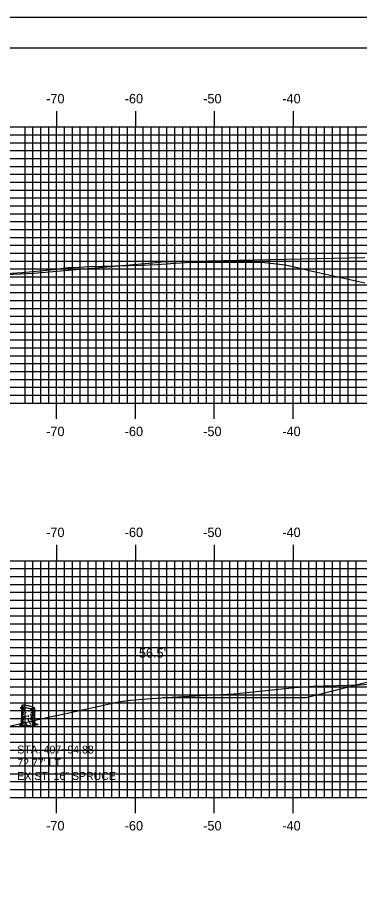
# Model space of a CAD drawing. Extents: x 852529 to 852872, y 364785 to 365005.
# Drawn here: x 852619.8 to 852663.2, y 364894.2 to 365005.1 of the extents above; entities that cross this region are included whole.
import ezdxf

# ---------------------------------------------------------------- set-up
doc = ezdxf.new("R2010")
doc.units = 0
for name, color, linetype in [('ANNOTATION', 7, 'Continuous'), ('BORDER', 7, 'Continuous'), ('D_Text_Monospaced', 7, 'Continuous'), ('D_Text_Standard', 7, 'Continuous'), ('H_V ANNOTATION', 7, 'Continuous'), ('MAJOR', 7, 'Continuous'), ('MINOR', 7, 'Continuous'), ('PLOT BOUNDARY', 7, 'Continuous'), ('S_Roadway_Centerline', 7, 'Continuous'), ('S_Trees_Conifer_Pay', 7, 'Continuous')]:
    doc.layers.add(name, color=color, linetype=linetype)

msp = doc.modelspace()

# ---------------------------------------------------------------- linework, layer by layer
at = {"layer": 'ANNOTATION'}
for p, q in [((852663.86, 364974.63), (852637.93, 364974.11)), ((852656.38, 364918.85), (852638.2, 364918.84))]:
    msp.add_line(p, q, dxfattribs=at)
for points in [[(852610.41, 364972.14), (852621.84, 364972.69), (852637.93, 364974.11)], [(852673.13, 364923.04), (852669.13, 364922.04), (852656.38, 364918.85)]]:
    msp.add_lwpolyline(points, dxfattribs=at)
at = {"layer": 'BORDER'}
msp.add_lwpolyline([(852545.13, 364791.23), (852865.13, 364791.23), (852865.13, 365001.23), (852545.13, 365001.23)], close=True, dxfattribs=at)
at = {"layer": 'MAJOR'}
for p, q in [((852624.73, 364993.24), (852624.73, 364991.23)), ((852634.73, 364993.24), (852634.73, 364991.23)), ((852644.73, 364993.24), (852644.73, 364991.23)), ((852654.73, 364993.24), (852654.73, 364991.23)), ((852554.73, 364991.23), (852834.73, 364991.23)), ((852554.73, 364991.23), (852834.73, 364991.23)), ((852624.73, 364956.23), (852624.73, 364991.23)), ((852634.73, 364956.23), (852634.73, 364991.23)), ((852644.73, 364956.23), (852644.73, 364991.23)), ((852654.73, 364956.23), (852654.73, 364991.23)), ((852554.73, 364986.23), (852834.73, 364986.23)), ((852554.73, 364981.23), (852834.73, 364981.23)), ((852554.73, 364976.23), (852834.73, 364976.23)), ((852554.73, 364971.23), (852834.73, 364971.23)), ((852554.73, 364966.23), (852834.73, 364966.23)), ((852554.73, 364961.23), (852834.73, 364961.23)), ((852554.73, 364956.23), (852834.73, 364956.23)), ((852554.73, 364956.23), (852834.73, 364956.23)), ((852624.73, 364954.23), (852624.73, 364956.23)), ((852634.73, 364954.23), (852634.73, 364956.23)), ((852644.73, 364954.23), (852644.73, 364956.23)), ((852654.73, 364954.23), (852654.73, 364956.23)), ((852624.73, 364938.24), (852624.73, 364936.23)), ((852634.73, 364938.24), (852634.73, 364936.23)), ((852644.73, 364938.24), (852644.73, 364936.23)), ((852654.73, 364938.24), (852654.73, 364936.23)), ((852554.73, 364936.23), (852834.73, 364936.23)), ((852554.73, 364936.23), (852834.73, 364936.23)), ((852624.73, 364906.23), (852624.73, 364936.23)), ((852634.73, 364906.23), (852634.73, 364936.23)), ((852644.73, 364906.23), (852644.73, 364936.23)), ((852654.73, 364906.23), (852654.73, 364936.23)), ((852554.73, 364931.23), (852834.73, 364931.23)), ((852554.73, 364926.23), (852834.73, 364926.23)), ((852554.73, 364921.23), (852834.73, 364921.23)), ((852554.73, 364916.23), (852834.73, 364916.23)), ((852554.73, 364911.23), (852834.73, 364911.23)), ((852554.73, 364906.23), (852834.73, 364906.23)), ((852554.73, 364906.23), (852834.73, 364906.23)), ((852624.73, 364904.23), (852624.73, 364906.23)), ((852634.73, 364904.23), (852634.73, 364906.23)), ((852644.73, 364904.23), (852644.73, 364906.23)), ((852654.73, 364904.23), (852654.73, 364906.23))]:
    msp.add_line(p, q, dxfattribs=at)
at = {"layer": 'MINOR'}
for p, q in [((852620.73, 364956.23), (852620.73, 364991.23)), ((852621.73, 364956.23), (852621.73, 364991.23)), ((852622.73, 364956.23), (852622.73, 364991.23)), ((852623.73, 364956.23), (852623.73, 364991.23)), ((852625.73, 364956.23), (852625.73, 364991.23)), ((852626.73, 364956.23), (852626.73, 364991.23)), ((852627.73, 364956.23), (852627.73, 364991.23)), ((852628.73, 364956.23), (852628.73, 364991.23)), ((852629.73, 364956.23), (852629.73, 364991.23)), ((852630.73, 364956.23), (852630.73, 364991.23)), ((852631.73, 364956.23), (852631.73, 364991.23)), ((852632.73, 364956.23), (852632.73, 364991.23)), ((852633.73, 364956.23), (852633.73, 364991.23)), ((852635.73, 364956.23), (852635.73, 364991.23)), ((852636.73, 364956.23), (852636.73, 364991.23)), ((852637.73, 364956.23), (852637.73, 364991.23)), ((852638.73, 364956.23), (852638.73, 364991.23)), ((852639.73, 364956.23), (852639.73, 364991.23)), ((852640.73, 364956.23), (852640.73, 364991.23)), ((852641.73, 364956.23), (852641.73, 364991.23)), ((852642.73, 364956.23), (852642.73, 364991.23)), ((852643.73, 364956.23), (852643.73, 364991.23)), ((852645.73, 364956.23), (852645.73, 364991.23)), ((852646.73, 364956.23), (852646.73, 364991.23)), ((852647.73, 364956.23), (852647.73, 364991.23)), ((852648.73, 364956.23), (852648.73, 364991.23)), ((852649.73, 364956.23), (852649.73, 364991.23)), ((852650.73, 364956.23), (852650.73, 364991.23)), ((852651.73, 364956.23), (852651.73, 364991.23)), ((852652.73, 364956.23), (852652.73, 364991.23)), ((852653.73, 364956.23), (852653.73, 364991.23)), ((852655.73, 364956.23), (852655.73, 364991.23)), ((852656.73, 364956.23), (852656.73, 364991.23)), ((852657.73, 364956.23), (852657.73, 364991.23)), ((852658.73, 364956.23), (852658.73, 364991.23)), ((852659.73, 364956.23), (852659.73, 364991.23)), ((852660.73, 364956.23), (852660.73, 364991.23)), ((852661.73, 364956.23), (852661.73, 364991.23)), ((852662.73, 364956.23), (852662.73, 364991.23)), ((852554.73, 364990.23), (852834.73, 364990.23)), ((852554.73, 364989.23), (852834.73, 364989.23)), ((852554.73, 364988.23), (852834.73, 364988.23)), ((852554.73, 364987.23), (852834.73, 364987.23)), ((852554.73, 364985.23), (852834.73, 364985.23)), ((852554.73, 364984.23), (852834.73, 364984.23)), ((852554.73, 364983.23), (852834.73, 364983.23)), ((852554.73, 364982.23), (852834.73, 364982.23)), ((852554.73, 364980.23), (852834.73, 364980.23)), ((852554.73, 364979.23), (852834.73, 364979.23)), ((852554.73, 364978.23), (852834.73, 364978.23)), ((852554.73, 364977.23), (852834.73, 364977.23)), ((852554.73, 364975.23), (852834.73, 364975.23)), ((852554.73, 364974.23), (852834.73, 364974.23)), ((852554.73, 364973.23), (852834.73, 364973.23)), ((852554.73, 364972.23), (852834.73, 364972.23)), ((852554.73, 364970.23), (852834.73, 364970.23)), ((852554.73, 364969.23), (852834.73, 364969.23)), ((852554.73, 364968.23), (852834.73, 364968.23)), ((852554.73, 364967.23), (852834.73, 364967.23)), ((852554.73, 364965.23), (852834.73, 364965.23)), ((852554.73, 364964.23), (852834.73, 364964.23)), ((852554.73, 364963.23), (852834.73, 364963.23)), ((852554.73, 364962.23), (852834.73, 364962.23)), ((852554.73, 364960.23), (852834.73, 364960.23)), ((852554.73, 364959.23), (852834.73, 364959.23)), ((852554.73, 364958.23), (852834.73, 364958.23)), ((852554.73, 364957.23), (852834.73, 364957.23)), ((852620.73, 364906.23), (852620.73, 364936.23)), ((852621.73, 364906.23), (852621.73, 364936.23)), ((852622.73, 364906.23), (852622.73, 364936.23)), ((852623.73, 364906.23), (852623.73, 364936.23)), ((852625.73, 364906.23), (852625.73, 364936.23)), ((852626.73, 364906.23), (852626.73, 364936.23)), ((852627.73, 364906.23), (852627.73, 364936.23)), ((852628.73, 364906.23), (852628.73, 364936.23)), ((852629.73, 364906.23), (852629.73, 364936.23)), ((852630.73, 364906.23), (852630.73, 364936.23)), ((852631.73, 364906.23), (852631.73, 364936.23)), ((852632.73, 364906.23), (852632.73, 364936.23)), ((852633.73, 364906.23), (852633.73, 364936.23)), ((852635.73, 364906.23), (852635.73, 364936.23)), ((852636.73, 364906.23), (852636.73, 364936.23)), ((852637.73, 364906.23), (852637.73, 364936.23)), ((852638.73, 364906.23), (852638.73, 364936.23)), ((852639.73, 364906.23), (852639.73, 364936.23)), ((852640.73, 364906.23), (852640.73, 364936.23)), ((852641.73, 364906.23), (852641.73, 364936.23)), ((852642.73, 364906.23), (852642.73, 364936.23)), ((852643.73, 364906.23), (852643.73, 364936.23)), ((852645.73, 364906.23), (852645.73, 364936.23)), ((852646.73, 364906.23), (852646.73, 364936.23)), ((852647.73, 364906.23), (852647.73, 364936.23)), ((852648.73, 364906.23), (852648.73, 364936.23)), ((852649.73, 364906.23), (852649.73, 364936.23)), ((852650.73, 364906.23), (852650.73, 364936.23)), ((852651.73, 364906.23), (852651.73, 364936.23)), ((852652.73, 364906.23), (852652.73, 364936.23)), ((852653.73, 364906.23), (852653.73, 364936.23)), ((852655.73, 364906.23), (852655.73, 364936.23)), ((852656.73, 364906.23), (852656.73, 364936.23)), ((852657.73, 364906.23), (852657.73, 364936.23)), ((852658.73, 364906.23), (852658.73, 364936.23)), ((852659.73, 364906.23), (852659.73, 364936.23)), ((852660.73, 364906.23), (852660.73, 364936.23)), ((852661.73, 364906.23), (852661.73, 364936.23)), ((852662.73, 364906.23), (852662.73, 364936.23)), ((852554.73, 364935.23), (852834.73, 364935.23)), ((852554.73, 364934.23), (852834.73, 364934.23)), ((852554.73, 364933.23), (852834.73, 364933.23)), ((852554.73, 364932.23), (852834.73, 364932.23)), ((852554.73, 364930.23), (852834.73, 364930.23)), ((852554.73, 364929.23), (852834.73, 364929.23)), ((852554.73, 364928.23), (852834.73, 364928.23)), ((852554.73, 364927.23), (852834.73, 364927.23)), ((852554.73, 364925.23), (852834.73, 364925.23)), ((852554.73, 364924.23), (852834.73, 364924.23)), ((852554.73, 364923.23), (852834.73, 364923.23)), ((852554.73, 364922.23), (852834.73, 364922.23)), ((852554.73, 364920.23), (852834.73, 364920.23)), ((852554.73, 364919.23), (852834.73, 364919.23)), ((852554.73, 364918.23), (852834.73, 364918.23)), ((852554.73, 364917.23), (852834.73, 364917.23)), ((852554.73, 364915.23), (852834.73, 364915.23)), ((852554.73, 364914.23), (852834.73, 364914.23)), ((852554.73, 364913.23), (852834.73, 364913.23)), ((852554.73, 364912.23), (852834.73, 364912.23)), ((852554.73, 364910.23), (852834.73, 364910.23)), ((852554.73, 364909.23), (852834.73, 364909.23)), ((852554.73, 364908.23), (852834.73, 364908.23)), ((852554.73, 364907.23), (852834.73, 364907.23))]:
    msp.add_line(p, q, dxfattribs=at)
at = {"layer": 'PLOT BOUNDARY'}
msp.add_lwpolyline([(852528.94, 364785.11), (852868.94, 364785.11), (852868.94, 365005.11), (852528.94, 365005.11)], close=True, dxfattribs=at)
at = {"layer": 'S_Roadway_Centerline'}
for points in [[(852610.84, 364972.19), (852620.36, 364972.79), (852624.32, 364973.16), (852626.18, 364973.4), (852626.86, 364973.43), (852628.9, 364973.52), (852635.5, 364973.73), (852637.51, 364973.8), (852637.99, 364973.83), (852641.71, 364974.09), (852649.77, 364974.09), (852650.73, 364974.09), (852653.38, 364973.78), (852653.64, 364973.75), (852653.75, 364973.77), (852654.14, 364973.68), (852656.37, 364973.17), (852656.63, 364973.07), (852663.86, 364971.49)], [(852610.61, 364913.39), (852623.86, 364916.43), (852624.73, 364916.6), (852625.73, 364916.82), (852632.57, 364918.34), (852634.09, 364918.54), (852636.22, 364918.74), (852638.65, 364918.87), (852643.03, 364919.13), (852647.2, 364919.36), (852654.94, 364920.14), (852657.27, 364920.33), (852663.16, 364920.51), (852665.08, 364920.61)]]:
    msp.add_lwpolyline(points, dxfattribs=at)
at = {"layer": 'S_Trees_Conifer_Pay'}
for p, q in [((852620.3, 364916.21), (852620.3, 364917.85)), ((852620.37, 364917.78), (852620.37, 364917.62)), ((852620.37, 364917.55), (852620.37, 364917.42)), ((852620.49, 364917.72), (852620.49, 364917.5)), ((852620.49, 364917.41), (852620.49, 364917.36)), ((852620.71, 364917.52), (852620.71, 364917.32)), ((852621.51, 364917.48), (852621.51, 364917.31)), ((852621.73, 364917.46), (852621.73, 364917.23)), ((852621.86, 364917.47), (852621.86, 364917.37)), ((852621.91, 364917.48), (852621.91, 364917.01)), ((852621.96, 364915.8), (852621.96, 364917.52)), ((852620.37, 364917.24), (852620.37, 364916.9)), ((852620.37, 364916.86), (852620.37, 364916.7)), ((852620.37, 364916.65), (852620.37, 364916.44)), ((852620.37, 364916.41), (852620.37, 364916.33)), ((852620.37, 364916.29), (852620.37, 364916.12)), ((852620.43, 364917.23), (852620.48, 364917.17)), ((852620.49, 364917.03), (852620.49, 364916.89)), ((852620.49, 364916.78), (852620.49, 364916.67)), ((852620.49, 364916.54), (852620.49, 364916.4)), ((852620.71, 364917.27), (852620.71, 364917.18)), ((852620.71, 364916.83), (852620.71, 364916.73)), ((852620.71, 364916.36), (852620.71, 364916.21)), ((852621.11, 364917.25), (852621.11, 364917.16)), ((852621.11, 364916.64), (852621.11, 364916.56)), ((852621.11, 364916.54), (852621.11, 364916.39)), ((852621.51, 364917.08), (852621.51, 364916.84)), ((852621.51, 364916.6), (852621.51, 364916.44)), ((852621.51, 364916.4), (852621.51, 364916.23)), ((852621.73, 364917.19), (852621.73, 364917.11)), ((852621.73, 364916.71), (852621.73, 364916.57)), ((852621.73, 364916.3), (852621.73, 364916.16)), ((852621.86, 364917.3), (852621.86, 364917.09)), ((852621.86, 364917.04), (852621.86, 364916.84)), ((852621.86, 364916.79), (852621.86, 364916.45)), ((852621.86, 364916.4), (852621.86, 364916.26)), ((852621.91, 364916.95), (852621.91, 364916.64)), ((852621.91, 364916.59), (852621.91, 364916.1)), ((852620.49, 364916.17), (852620.49, 364916)), ((852620.71, 364915.98), (852620.71, 364915.89)), ((852621.11, 364916.1), (852621.11, 364915.94)), ((852621.29, 364915.34), (852621.42, 364915.4)), ((852621.51, 364915.95), (852621.51, 364915.8)), ((852621.73, 364915.4), (852621.57, 364915.47)), ((852621.73, 364915.9), (852621.73, 364915.8)), ((852621.86, 364916.17), (852621.86, 364915.79)), ((852621.91, 364916.04), (852621.91, 364915.8))]:
    msp.add_line(p, q, dxfattribs=at)
for points in [[(852620.25, 364917.58), (852620.18, 364917.59), (852620.1, 364917.49)], [(852620.48, 364917.35), (852620.44, 364917.28), (852620.4, 364917.33), (852620.34, 364917.4), (852620.25, 364917.6), (852620.18, 364917.64), (852620.15, 364917.65)], [(852620.47, 364917.1), (852620.43, 364917.23), (852620.37, 364917.34), (852620.33, 364917.41), (852620.27, 364917.55)], [(852620.51, 364917.31), (852620.54, 364917.23), (852620.55, 364917.16), (852620.52, 364917.1)], [(852620.64, 364916.43), (852620.63, 364916.35), (852620.58, 364916.36), (852620.6, 364916.53)], [(852621.78, 364916.82), (852621.79, 364916.92), (852621.74, 364916.9), (852621.74, 364916.8)], [(852620.3, 364916.21), (852620.25, 364915.94), (852620.23, 364915.67), (852620.17, 364915.55), (852620.04, 364915.51), (852620.27, 364915.48), (852620.27, 364915.48), (852620.26, 364915.43), (852620.01, 364915.34), (852620.29, 364915.35), (852620.64, 364915.37), (852620.96, 364915.36), (852620.96, 364915.44), (852621.11, 364915.36), (852621.29, 364915.34), (852621.27, 364915.27), (852621.54, 364915.31), (852621.76, 364915.29), (852622.05, 364915.3), (852621.76, 364915.36), (852621.73, 364915.4), (852621.89, 364915.46), (852622.13, 364915.47), (852622.37, 364915.47), (852622.03, 364915.53), (852621.99, 364915.61), (852621.96, 364915.8)], [(852620.47, 364915.92), (852620.4, 364915.81), (852620.39, 364915.64), (852620.27, 364915.48)], [(852620.37, 364916.06), (852620.37, 364915.92), (852620.32, 364915.85), (852620.31, 364915.65)], [(852620.43, 364915.42), (852620.44, 364915.56), (852620.52, 364915.69)], [(852620.71, 364915.81), (852620.7, 364915.69), (852620.62, 364915.64)], [(852620.96, 364915.44), (852620.88, 364915.59), (852620.87, 364915.69)], [(852621.45, 364915.51), (852621.38, 364915.61), (852621.35, 364915.75)], [(852621.67, 364915.76), (852621.67, 364915.62), (852621.76, 364915.52)], [(852621.84, 364915.73), (852621.83, 364915.61), (852621.88, 364915.52), (852621.89, 364915.46)], [(852621.91, 364915.75), (852621.93, 364915.67), (852621.95, 364915.58)]]:
    msp.add_lwpolyline(points, dxfattribs=at)
for centre, radius, start, end in [((852620.32, 364917.85), 0.0264, 145.7806, 156.5926), ((852620.33, 364917.85), 0.0314, 133.077, 145.7806), ((852620.32, 364917.85), 0.0226, 156.5926, 168.2806), ((852620.32, 364917.85), 0.0226, 168.2806, 179.9685), ((852620.33, 364917.85), 0.0314, 190.7806, 203.4842), ((852620.32, 364917.85), 0.0264, 179.9685, 190.7806), ((852620.35, 364917.86), 0.0527, 203.4842, 213.2806), ((852620.37, 364917.88), 0.0817, 213.2806, 227.6113), ((852620.34, 364917.73), 0.0441, 196.0515, 210), ((852620.33, 364917.73), 0.0334, 185.7849, 196.0515), ((852620.36, 364917.74), 0.0624, 210, 228.7494), ((852620.33, 364917.57), 0.0334, 185.7849, 196.0515), ((852620.34, 364917.58), 0.0441, 196.0515, 210), ((852620.36, 364917.58), 0.0624, 210, 228.7494), ((852620.36, 364917.81), 0.0817, 108.9499, 123.2806), ((852620.34, 364917.83), 0.0527, 123.2806, 133.077), ((852620.49, 364918), 0.251, 227.6113, 235.7806), ((852620.43, 364917.82), 0.172, 228.7494, 240), ((852620.43, 364917.67), 0.172, 228.7494, 240), ((852620.41, 364917.65), 0.251, 100.7806, 108.9499), ((852620.63, 364918.01), 0.571, 240, 242.9763), ((852620.8, 364918.46), 0.802, 235.7806, 251.9406), ((852620.52, 364917.11), 0.802, 84.6206, 100.7806), ((852620.63, 364918.17), 0.571, 247.5868, 255.5683), ((852620.63, 364918.01), 0.571, 255.6333, 261.8968), ((852622.15, 364922.62), 5.18, 251.9406, 258.2806), ((852621.13, 364921.53), 4.12, 261.8968, 263.762), ((852620.11, 364912.75), 5.18, 78.2806, 84.6206), ((852622.15, 364922.62), 5.18, 258.2806, 264.6206), ((852620.11, 364912.75), 5.18, 71.9406, 78.2806), ((852621.13, 364921.53), 4.12, 273.2669, 275.3045), ((852621.74, 364918.26), 0.802, 264.6206, 280.7806), ((852621.46, 364916.91), 0.802, 55.7806, 71.9406), ((852621.85, 364917.72), 0.251, 280.7806, 288.9499), ((852621.77, 364917.37), 0.251, 47.6113, 55.7806), ((852621.9, 364917.56), 0.0817, 288.9499, 303.2806), ((852621.89, 364917.49), 0.0817, 33.2806, 47.6113), ((852621.91, 364917.51), 0.0527, 23.4842, 33.2806), ((852621.93, 364917.52), 0.0314, 313.077, 325.7806), ((852621.92, 364917.54), 0.0527, 303.2806, 313.077), ((852621.93, 364917.52), 0.0314, 10.7806, 23.4842), ((852621.93, 364917.52), 0.0264, 359.9685, 10.7806), ((852621.94, 364917.52), 0.0226, 348.2806, 359.9685), ((852621.94, 364917.52), 0.0226, 336.5926, 348.2806), ((852621.94, 364917.52), 0.0264, 325.7806, 336.5926), ((852620.33, 364917.13), 0.0334, 185.7849, 196.0515), ((852620.33, 364916.89), 0.0334, 185.7849, 196.0515), ((852620.34, 364916.9), 0.0441, 196.0515, 210), ((852620.36, 364916.91), 0.0624, 210, 228.7494), ((852620.33, 364916.68), 0.0334, 185.7849, 196.0515), ((852620.34, 364916.69), 0.0441, 196.0515, 210), ((852620.36, 364916.7), 0.0624, 210, 228.7494), ((852620.33, 364916.25), 0.0334, 185.7849, 196.0515), ((852620.43, 364916.99), 0.172, 228.7494, 240), ((852620.43, 364916.78), 0.172, 228.7494, 240), ((852620.63, 364917.33), 0.571, 240, 242.8104), ((852620.63, 364917.12), 0.571, 240, 242.8104), ((852620.63, 364917.57), 0.571, 242.9571, 255.5507), ((852620.63, 364916.89), 0.571, 242.8104, 254.6017), ((852620.63, 364917.33), 0.571, 253.0704, 261.8968), ((852621.13, 364920.85), 4.12, 261.8968, 262.3875), ((852621.13, 364921.3), 4.12, 262.9442, 264.2151), ((852621.13, 364921.09), 4.12, 264.0496, 266.2948), ((852621.13, 364920.64), 4.12, 264.5431, 266.8507), ((852621.13, 364921.3), 4.12, 269.6419, 270), ((852621.13, 364920.64), 4.12, 269.6419, 270), ((852621.13, 364921.3), 4.12, 270, 271.9249), ((852621.13, 364920.85), 4.12, 273.3324, 275.919), ((852621.13, 364920.4), 4.12, 273.6807, 275.284), ((852621.13, 364920.64), 4.12, 276.8526, 278.1032), ((852621.63, 364917.12), 0.571, 278.1032, 280.7293), ((852621.63, 364917.78), 0.571, 282.0154, 293.1403), ((852621.63, 364917.57), 0.571, 292.9413, 300), ((852621.63, 364917.12), 0.571, 293.1403, 300), ((852621.63, 364916.89), 0.571, 293.1403, 300), ((852621.63, 364917.78), 0.571, 299.6633, 300), ((852621.63, 364917.33), 0.571, 299.6633, 300), ((852621.83, 364917.43), 0.172, 300, 311.2506), ((852621.83, 364916.99), 0.172, 300, 311.2506), ((852621.83, 364916.78), 0.172, 300, 311.2506), ((852621.83, 364916.54), 0.172, 300, 311.2506), ((852621.9, 364917.35), 0.0624, 311.2506, 330), ((852621.9, 364916.91), 0.0624, 311.2506, 330), ((852621.9, 364916.7), 0.0624, 311.2506, 330), ((852621.9, 364916.46), 0.0624, 311.2506, 330), ((852621.93, 364917.34), 0.0334, 0, 16.0515), ((852621.93, 364917.34), 0.0334, 343.9485, 360), ((852621.92, 364917.34), 0.0441, 330, 343.9485), ((852621.93, 364916.89), 0.0334, 0, 16.0515), ((852621.93, 364916.89), 0.0334, 343.9485, 360), ((852621.92, 364916.9), 0.0441, 330, 343.9485), ((852621.93, 364916.68), 0.0334, 0, 16.0515), ((852621.93, 364916.68), 0.0334, 343.9485, 360), ((852621.92, 364916.69), 0.0441, 330, 343.9485), ((852621.93, 364916.45), 0.0334, 0, 16.0515), ((852621.93, 364916.45), 0.0334, 343.9485, 360), ((852621.92, 364916.45), 0.0441, 330, 343.9485), ((852621.93, 364916.25), 0.0334, 0, 16.0515), ((852620.34, 364916.25), 0.0441, 196.0515, 210), ((852620.36, 364916.26), 0.0624, 210, 228.7494), ((852620.33, 364915.83), 0.0334, 185.7849, 196.0515), ((852620.34, 364915.84), 0.0441, 196.0515, 210), ((852620.36, 364915.84), 0.0624, 210, 228.7494), ((852620.43, 364916.34), 0.172, 228.7494, 240), ((852620.43, 364915.93), 0.172, 228.7494, 240), ((852620.63, 364916.69), 0.571, 240, 250.7093), ((852620.63, 364916.49), 0.571, 242.7279, 251.4933), ((852620.63, 364916.27), 0.571, 258.363, 261.8968), ((852621.13, 364919.79), 4.12, 261.8968, 262.6316), ((852621.13, 364920.01), 4.12, 263.2104, 264.2151), ((852621.13, 364920.01), 4.12, 269.8672, 270), ((852621.13, 364920.01), 4.12, 270, 272.1883), ((852621.13, 364920.21), 4.12, 274.1603, 276.5009), ((852621.13, 364919.79), 4.12, 276.488, 277.5562), ((852621.64, 364916.69), 0.571, 291.9732, 298.7631), ((852621.63, 364916.49), 0.571, 293.1403, 300), ((852621.63, 364916.27), 0.571, 295.4686, 300), ((852621.83, 364916.15), 0.172, 300, 311.2506), ((852621.83, 364915.93), 0.172, 300, 311.2506), ((852621.9, 364916.07), 0.0624, 311.2506, 330), ((852621.9, 364915.84), 0.0624, 311.2506, 330), ((852621.93, 364916.05), 0.0334, 0, 16.0515), ((852621.93, 364916.05), 0.0334, 343.9485, 360), ((852621.92, 364916.06), 0.0441, 330, 343.9485), ((852621.93, 364915.83), 0.0334, 0, 16.0515), ((852621.93, 364915.83), 0.0334, 343.9485, 360), ((852621.92, 364915.84), 0.0441, 330, 343.9485)]:
    msp.add_arc(centre, radius, start, end, dxfattribs=at)

# ---------------------------------------------------------------- texts
at = {"layer": 'D_Text_Monospaced'}
for s, p in [('STA. 407+94.88', (852619.74, 364911.79)), ("72.77' LT.", (852619.74, 364910.12)), ('EXIST. 16" SPRUCE', (852619.74, 364908.44))]:
    msp.add_text(s, height=1, dxfattribs=at).set_placement(p)
at = {"layer": 'D_Text_Standard'}
msp.add_text("56.5'", height=1.2, dxfattribs=at).set_placement((852635.18, 364923.94))
at = {"layer": 'H_V ANNOTATION'}
for s, p in [('-70', (852623.41, 364994.23)), ('-60', (852633.38, 364994.23)), ('-50', (852643.34, 364994.23)), ('-40', (852653.38, 364994.23)), ('-70', (852623.41, 364952.03)), ('-60', (852633.38, 364952.03)), ('-50', (852643.34, 364952.03)), ('-40', (852653.38, 364952.03)), ('-70', (852623.41, 364939.23)), ('-60', (852633.38, 364939.23)), ('-50', (852643.34, 364939.23)), ('-40', (852653.38, 364939.23)), ('-70', (852623.41, 364902.03)), ('-60', (852633.38, 364902.03)), ('-50', (852643.34, 364902.03)), ('-40', (852653.38, 364902.03))]:
    msp.add_text(s, height=1.2, dxfattribs=at).set_placement(p)
at = {"layer": 'S_Roadway_Centerline'}
for s, p in [('L', (852626.17, 364973.39)), ('C', (852626.18, 364973.4)), ('L', (852657.26, 364920.33)), ('C', (852657.27, 364920.33))]:
    msp.add_text(s, height=0.0146, dxfattribs=at).set_placement(p)

doc.saveas('drawing.dxf')
